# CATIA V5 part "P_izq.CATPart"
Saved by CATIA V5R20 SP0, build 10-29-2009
Part number: P_izq
Bounding box of the stored display mesh (mm): x 0 to 40, y -0.181 to 64.919, z -20 to 10
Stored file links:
  C:\Users\Ricardo\Desktop\Nueva carpeta (3)\P_izq.CATPart
  C:\Archivos de programa\Dassault Systemes\B20\intel_a\reffiles\standard\MetricThinPitch.txt
  C:\Archivos de programa\Dassault Systemes\B20\intel_a\reffiles\standard\MetricThickPitch.txt
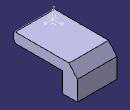
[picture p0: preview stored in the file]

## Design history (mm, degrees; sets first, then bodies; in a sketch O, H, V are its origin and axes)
AxisSystem1: origin (0, 0, 0), X (1, 0, 0), Y (0, 1, 0), Z (0, 0, 1)
Body1 (main body)
  Sketch1 on YZ plane of AxisSystem1, origin (0, 0, 0), H (0, 1, 0), V (0, 0, 1)
    line L1 (2.2121, 0) -> (0.1402, 3.1055)
    line L2 (-0.1813, 4.2672) -> (0, 8)
    point P1 (0, 8)
    arc A1 centre (1.7415, 4.1739) radius 1.925 from (-0.1813, 4.2672) to (0.1402, 3.1055) ccw
    line L3 (0, 8) -> (0, 10)
    point P5 (0, 10)
    line L4 (0, 10) -> (56.5282, 10)
    point P6 (2.2121, 0)
    line L5 (2.2121, 0) -> (49.9192, 0)
    line L6 (56.5282, 10) -> (64.9192, 0)
    point P7 (56.5282, 10)
    point P8 (64.9192, 0)
    line L7 (64.9192, 0) -> (64.9192, -20)
    point P9 (64.9192, 0)
    line L8 (64.9192, -20) -> (49.9192, -20)
    line L9 (49.9192, -20) -> (49.9192, 0)
    radius A1 = 1.925
    distance P1 H = 8
    angle L1 H = 123.71
    angle L2 H = 92.78
    length L1 = 3.7332
    length L3 = 2
    angle L5 L6 = 50
    length L7 = 20
    length L8 = 15
    distance P7 L3 = 56.5282
    tangency: A1 L2, A1 L1
    vertical: L3 V, L7 V, L9 V
    horizontal: L4 H, L5 H, L8 H
    coincidence: P5 V, P6 H, P9 P8, P8 H
  Pad1: profile Sketch1, direction (1, 0, 0), length 40
  Fillet1: radius 2, on edge [face of Pad1 from Sketch1.L3 | face of Pad1 from Sketch1.L4]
